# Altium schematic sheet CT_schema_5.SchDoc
size 372 x 328 mm
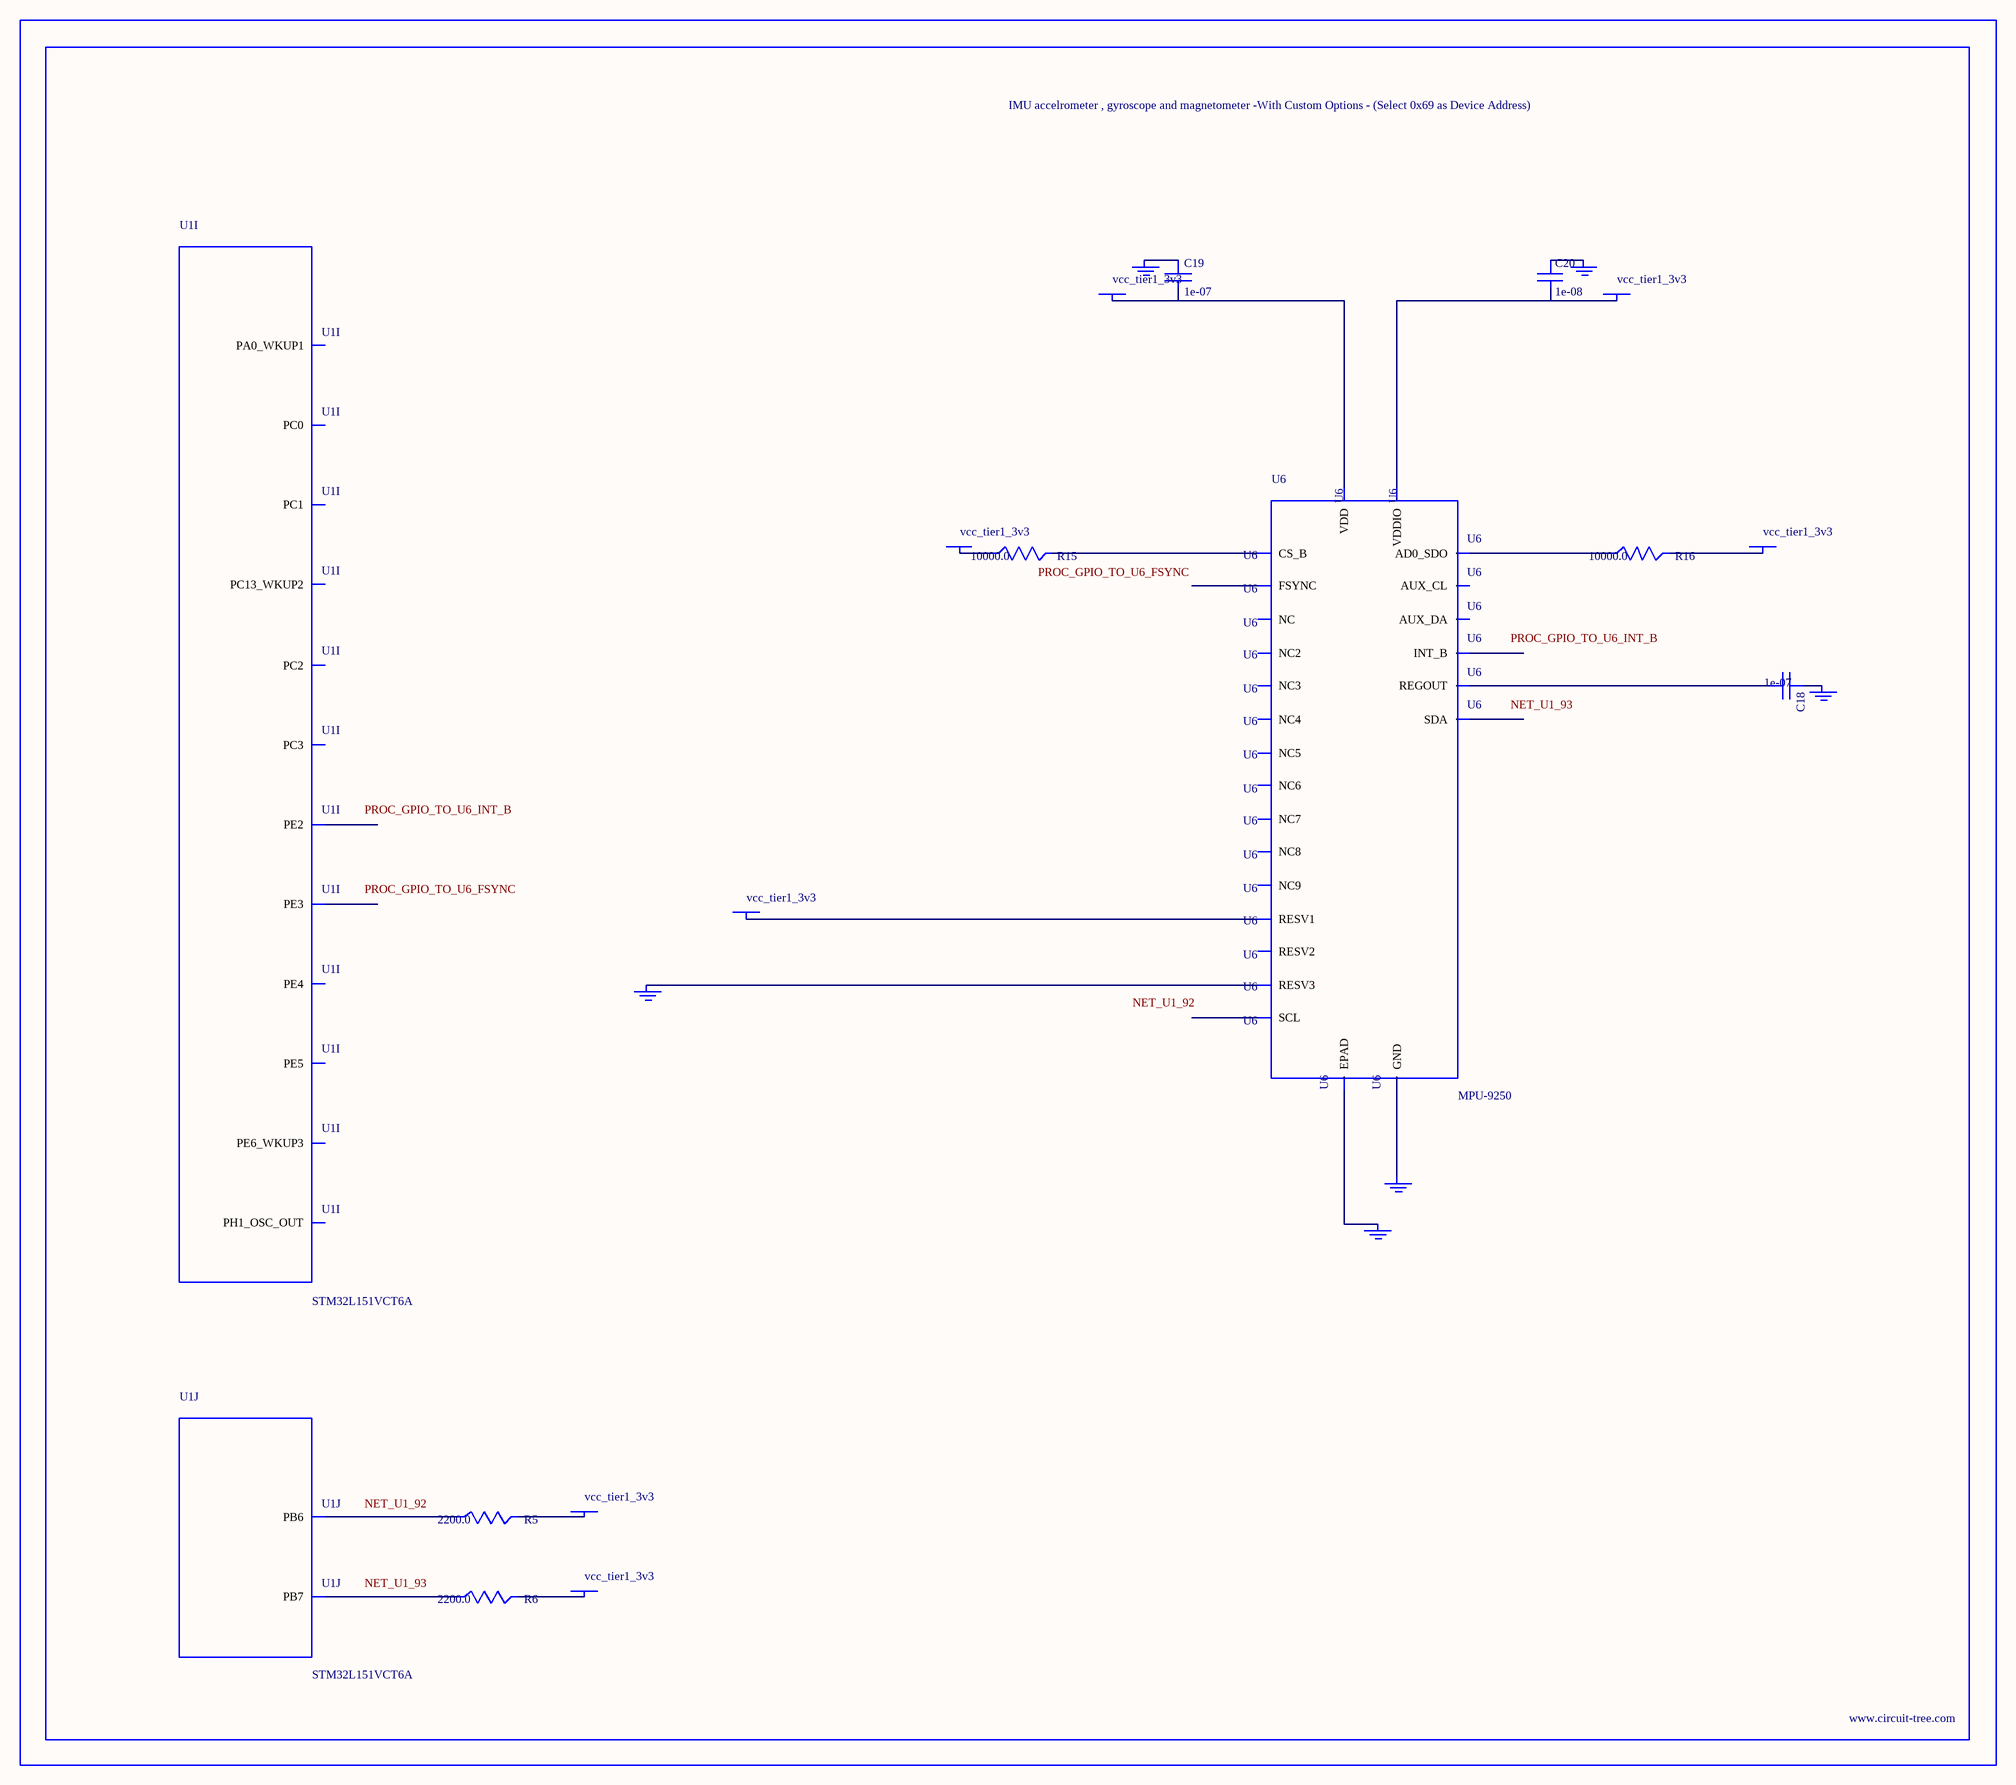
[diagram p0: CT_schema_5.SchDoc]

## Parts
BORDER4  (no value)
C18  1e-07  [C0402]
C19  1e-07  [C0402]
C20  1e-08  [C0402]
GND_INSTANCE_4_0  (no value)
GND_INSTANCE_4_1  (no value)
GND_INSTANCE_4_2  (no value)
GND_INSTANCE_4_3  (no value)
GND_INSTANCE_4_4  (no value)
GND_INSTANCE_4_5  (no value)
POWER_INSTANCE_4_0  vcc_tier1_3v3
POWER_INSTANCE_4_1  vcc_tier1_3v3
POWER_INSTANCE_4_2  vcc_tier1_3v3
POWER_INSTANCE_4_3  vcc_tier1_3v3
POWER_INSTANCE_4_4  vcc_tier1_3v3
POWER_INSTANCE_4_5  vcc_tier1_3v3
POWER_INSTANCE_4_6  vcc_tier1_3v3
R5  2200.0  [R0603]
R6  2200.0  [R0603]
R15  10000.0  [R0603]
R16  10000.0  [R0603]
U1  STM32L151VCT6A  [LQFP100]  (parts I,J of 10)
U6  MPU-9250  [QFN24_2]

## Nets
NetC18_1: C18.1 GND_INSTANCE_4_1.0(GND)
NetC18_2: C18.2 U6.10(REGOUT)
NetC19_1: C19.1 GND_INSTANCE_4_2.0(GND)
NetC19_2: C19.2 POWER_INSTANCE_4_3.0(PWR) U6.13(VDD)
NetC20_1: C20.1 GND_INSTANCE_4_0.0(GND)
NetC20_2: C20.2 POWER_INSTANCE_4_1.0(PWR) U6.8(VDDIO)
NetGND_INSTANCE_4_3_0: GND_INSTANCE_4_3.0(GND) U6.20(RESV3)
NetGND_INSTANCE_4_4_0: GND_INSTANCE_4_4.0(GND) U6.25(EPAD)
NetGND_INSTANCE_4_5_0: GND_INSTANCE_4_5.0(GND) U6.18(GND)
NetPOWER_INSTANCE_4_0_0: POWER_INSTANCE_4_0.0(PWR) U6.1(RESV1)
NetPOWER_INSTANCE_4_2_0: POWER_INSTANCE_4_2.0(PWR) R16.2
NetPOWER_INSTANCE_4_4_0: POWER_INSTANCE_4_4.0(PWR) R15.1
NetPOWER_INSTANCE_4_5_0: POWER_INSTANCE_4_5.0(PWR) R5.2
NetPOWER_INSTANCE_4_6_0: POWER_INSTANCE_4_6.0(PWR) R6.2
NetR5_1: R5.1 U1.92(PB6)
NetR6_1: R6.1 U1.93(PB7)
NetR15_2: R15.2 U6.22(CS_B)
NetR16_1: R16.1 U6.9(AD0_SDO)

Not connected (* = marked no-connect by the designer): U1 1(PE2) 2(PE3) 3(PE4) 4(PE5) 5(PE6_WKUP3) 7(PC13_WKUP2) 13(PH1_OSC_OUT) 15(PC0) 16(PC1) 17(PC2) 18(PC3) 23(PA0_WKUP1); U6 2(NC) 3(NC2) 4(NC3) 5(NC4) 6(NC5) 7(AUX_CL) 11(FSYNC) 12(INT_B) 14(NC6) 15(NC7) 16(NC8) 17(NC9) 19(RESV2) 21(AUX_DA) 23(SCL) 24(SDA)

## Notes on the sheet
- Labels drawn without touching a wire or pin: NET_U1_92, NET_U1_93, PROC_GPIO_TO_U6_FSYNC, PROC_GPIO_TO_U6_INT_B

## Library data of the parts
BORDER4 = BORDER_PAGE4
C18 C19 = C0402C104K3RACTU
C20 = C0402C103K3RAC
GND_INSTANCE_4_0-GND_INSTANCE_4_5 = GND
POWER_INSTANCE_4_0-POWER_INSTANCE_4_6 = PWR
R5 R6 = RC0603JR-072K2L
R15 R16 = RC0603JR-0710KL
